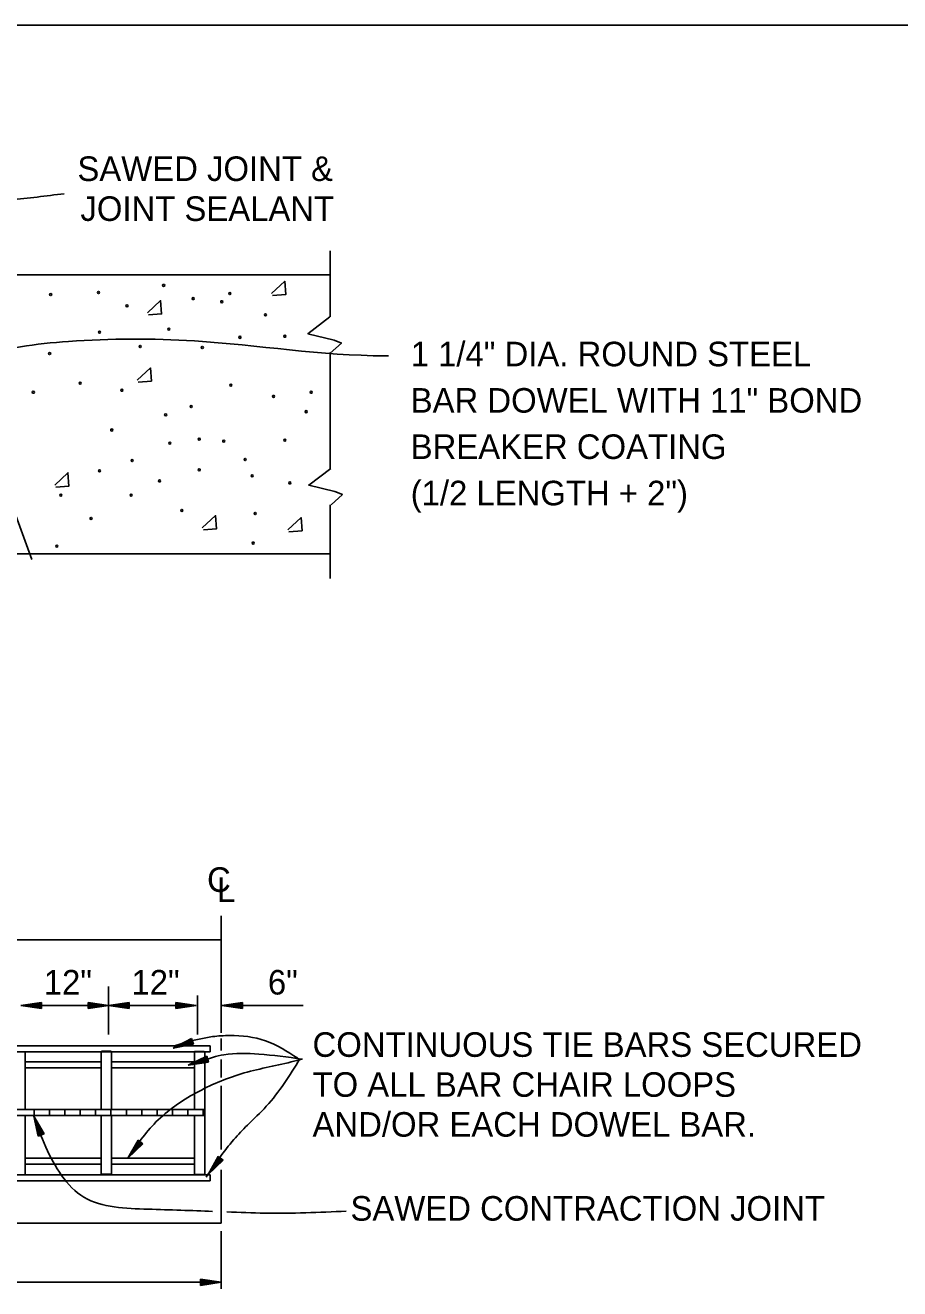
# Model space of a CAD drawing. Extents: x 1375738 to 1375905, y 380661 to 380875.
# Drawn here: x 1375765.86 to 1375781.94, y 380791.56 to 380814.78 of the extents above; entities that cross this region are included whole.
import ezdxf

# ---------------------------------------------------------------- set-up
doc = ezdxf.new("R2010")
doc.units = 0
doc.layers.add('R_Border', color=7, linetype='Continuous')
doc.layers.add('R_Draft', color=7, linetype='Continuous')

msp = doc.modelspace()

# ---------------------------------------------------------------- linework, layer by layer
at = {"layer": 'R_Border'}
msp.add_line((1375744.419, 380814.777), (1375786.095, 380814.777), dxfattribs=at)
at = {"layer": 'R_Draft'}
for p, q in [((1375771.466, 380809.419), (1375771.466, 380810.635)), ((1375759.477, 380810.189), (1375771.466, 380810.189)), ((1375771.466, 380806.625), (1375771.466, 380808.767)), ((1375764.849, 380808.047), (1375765.982, 380804.959)), ((1375771.466, 380804.614), (1375771.466, 380805.963)), ((1375747.021, 380805.063), (1375771.466, 380805.063)), ((1375769.46, 380796.263), (1375769.46, 380798.416)), ((1375759.021, 380797.97), (1375769.46, 380797.97)), ((1375767.391, 380796.231), (1375767.391, 380797.112)), ((1375766.156, 380796.822), (1375765.78, 380796.765)), ((1375765.78, 380796.765), (1375767.391, 380796.765)), ((1375766.156, 380796.709), (1375765.78, 380796.765)), ((1375766.156, 380796.813), (1375765.843, 380796.765)), ((1375766.156, 380796.718), (1375765.843, 380796.765)), ((1375766.156, 380796.803), (1375765.908, 380796.765)), ((1375766.156, 380796.728), (1375765.908, 380796.765)), ((1375766.156, 380796.793), (1375765.97, 380796.765)), ((1375766.156, 380796.738), (1375765.97, 380796.765)), ((1375766.156, 380796.784), (1375766.034, 380796.765)), ((1375766.156, 380796.747), (1375766.034, 380796.765)), ((1375766.156, 380796.774), (1375766.096, 380796.765)), ((1375766.156, 380796.757), (1375766.096, 380796.765)), ((1375766.156, 380796.709), (1375766.156, 380796.822)), ((1375767.015, 380796.822), (1375767.391, 380796.765)), ((1375767.015, 380796.822), (1375767.015, 380796.709)), ((1375767.015, 380796.813), (1375767.328, 380796.765)), ((1375767.015, 380796.803), (1375767.264, 380796.765)), ((1375767.015, 380796.793), (1375767.201, 380796.765)), ((1375767.015, 380796.783), (1375767.137, 380796.765)), ((1375767.015, 380796.774), (1375767.074, 380796.765)), ((1375767.015, 380796.709), (1375767.391, 380796.765)), ((1375767.015, 380796.747), (1375767.137, 380796.765)), ((1375767.015, 380796.728), (1375767.264, 380796.765)), ((1375767.015, 380796.718), (1375767.328, 380796.765)), ((1375767.015, 380796.738), (1375767.201, 380796.765)), ((1375767.015, 380796.757), (1375767.074, 380796.765)), ((1375767.768, 380796.822), (1375767.391, 380796.765)), ((1375767.391, 380796.765), (1375769.003, 380796.765)), ((1375767.768, 380796.709), (1375767.391, 380796.765)), ((1375767.768, 380796.813), (1375767.454, 380796.765)), ((1375767.768, 380796.718), (1375767.454, 380796.765)), ((1375767.768, 380796.803), (1375767.519, 380796.765)), ((1375767.768, 380796.728), (1375767.519, 380796.765)), ((1375767.768, 380796.793), (1375767.581, 380796.765)), ((1375767.768, 380796.738), (1375767.581, 380796.765)), ((1375767.768, 380796.784), (1375767.645, 380796.765)), ((1375767.768, 380796.747), (1375767.645, 380796.765)), ((1375767.768, 380796.774), (1375767.708, 380796.765)), ((1375767.768, 380796.757), (1375767.708, 380796.765)), ((1375767.768, 380796.709), (1375767.768, 380796.822)), ((1375768.626, 380796.822), (1375769.003, 380796.765)), ((1375768.626, 380796.822), (1375768.626, 380796.709)), ((1375768.626, 380796.813), (1375768.94, 380796.765)), ((1375768.626, 380796.803), (1375768.875, 380796.765)), ((1375768.626, 380796.793), (1375768.813, 380796.765)), ((1375768.626, 380796.783), (1375768.749, 380796.765)), ((1375768.626, 380796.774), (1375768.686, 380796.765)), ((1375768.626, 380796.709), (1375769.003, 380796.765)), ((1375768.626, 380796.747), (1375768.749, 380796.765)), ((1375768.626, 380796.728), (1375768.875, 380796.765)), ((1375768.626, 380796.718), (1375768.94, 380796.765)), ((1375768.626, 380796.738), (1375768.813, 380796.765)), ((1375768.626, 380796.757), (1375768.686, 380796.765)), ((1375769.025, 380796.231), (1375769.025, 380796.947)), ((1375769.85, 380796.822), (1375769.473, 380796.765)), ((1375769.473, 380796.765), (1375770.968, 380796.765)), ((1375769.85, 380796.709), (1375769.473, 380796.765)), ((1375769.85, 380796.813), (1375769.536, 380796.765)), ((1375769.85, 380796.718), (1375769.536, 380796.765)), ((1375769.85, 380796.803), (1375769.601, 380796.765)), ((1375769.85, 380796.728), (1375769.601, 380796.765)), ((1375769.85, 380796.793), (1375769.663, 380796.765)), ((1375769.85, 380796.738), (1375769.663, 380796.765)), ((1375769.85, 380796.784), (1375769.727, 380796.765)), ((1375769.85, 380796.747), (1375769.727, 380796.765)), ((1375769.85, 380796.774), (1375769.79, 380796.765)), ((1375769.85, 380796.757), (1375769.79, 380796.765)), ((1375769.85, 380796.709), (1375769.85, 380796.822)), ((1375768.912, 380796.162), (1375768.578, 380795.98)), ((1375768.95, 380796.057), (1375768.578, 380795.98)), ((1375768.914, 380796.154), (1375768.637, 380796.001)), ((1375768.947, 380796.065), (1375768.637, 380796.001)), ((1375768.918, 380796.145), (1375768.697, 380796.023)), ((1375768.944, 380796.074), (1375768.697, 380796.023)), ((1375768.921, 380796.136), (1375768.756, 380796.045)), ((1375768.941, 380796.083), (1375768.756, 380796.045)), ((1375768.925, 380796.127), (1375768.816, 380796.067)), ((1375768.937, 380796.093), (1375768.816, 380796.067)), ((1375768.928, 380796.118), (1375768.875, 380796.089)), ((1375768.934, 380796.101), (1375768.875, 380796.089)), ((1375768.95, 380796.057), (1375768.912, 380796.162)), ((1375769.46, 380795.936), (1375769.46, 380796.159)), ((1375751.127, 380796.025), (1375769.258, 380796.025)), ((1375751.127, 380795.912), (1375769.258, 380795.912)), ((1375765.86, 380794.863), (1375765.86, 380795.926)), ((1375767.257, 380794.863), (1375767.257, 380795.926)), ((1375767.258, 380795.926), (1375767.435, 380795.926)), ((1375767.445, 380794.863), (1375767.445, 380795.926)), ((1375769.194, 380795.832), (1375768.852, 380795.667)), ((1375769.197, 380795.824), (1375768.912, 380795.685)), ((1375768.972, 380794.855), (1375768.972, 380795.919)), ((1375768.973, 380795.919), (1375769.15, 380795.919)), ((1375769.2, 380795.814), (1375768.974, 380795.704)), ((1375769.203, 380795.805), (1375769.033, 380795.723)), ((1375769.16, 380793.662), (1375769.16, 380795.919)), ((1375769.228, 380795.724), (1375769.194, 380795.832)), ((1375769.258, 380796.025), (1375769.258, 380795.912)), ((1375765.86, 380795.731), (1375767.257, 380795.731)), ((1375765.86, 380795.618), (1375767.257, 380795.618)), ((1375767.445, 380795.731), (1375768.966, 380795.731)), ((1375767.445, 380795.618), (1375768.966, 380795.618)), ((1375769.228, 380795.724), (1375768.852, 380795.667)), ((1375769.225, 380795.734), (1375768.912, 380795.685)), ((1375769.222, 380795.743), (1375768.974, 380795.704)), ((1375769.22, 380795.751), (1375769.033, 380795.723)), ((1375769.206, 380795.796), (1375769.094, 380795.742)), ((1375769.217, 380795.76), (1375769.094, 380795.742)), ((1375769.208, 380795.786), (1375769.154, 380795.76)), ((1375769.214, 380795.77), (1375769.154, 380795.76)), ((1375769.46, 380795.442), (1375769.46, 380795.776)), ((1375769.46, 380794.121), (1375769.46, 380795.287)), ((1375751.202, 380794.857), (1375769.16, 380794.857)), ((1375751.202, 380794.744), (1375769.16, 380794.744)), ((1375765.86, 380793.669), (1375765.86, 380794.751)), ((1375766.099, 380794.364), (1375766.016, 380794.735)), ((1375766.205, 380794.405), (1375766.016, 380794.735)), ((1375766.023, 380794.751), (1375766.023, 380794.853)), ((1375766.108, 380794.367), (1375766.038, 380794.677)), ((1375766.196, 380794.401), (1375766.038, 380794.677)), ((1375766.306, 380794.751), (1375766.306, 380794.853)), ((1375766.588, 380794.751), (1375766.588, 380794.853)), ((1375766.87, 380794.751), (1375766.87, 380794.853)), ((1375767.152, 380794.751), (1375767.152, 380794.853)), ((1375767.257, 380793.669), (1375767.257, 380794.751)), ((1375767.434, 380794.751), (1375767.434, 380794.853)), ((1375767.445, 380793.669), (1375767.445, 380794.751)), ((1375767.717, 380794.751), (1375767.717, 380794.853)), ((1375767.999, 380794.751), (1375767.999, 380794.853)), ((1375768.281, 380794.751), (1375768.281, 380794.853)), ((1375768.564, 380794.751), (1375768.564, 380794.853)), ((1375768.846, 380794.751), (1375768.846, 380794.853)), ((1375768.972, 380793.662), (1375768.972, 380794.738)), ((1375769.128, 380794.751), (1375769.128, 380794.853)), ((1375766.187, 380794.398), (1375766.062, 380794.617)), ((1375766.117, 380794.371), (1375766.062, 380794.617)), ((1375766.126, 380794.375), (1375766.084, 380794.558)), ((1375766.178, 380794.394), (1375766.084, 380794.558)), ((1375766.099, 380794.364), (1375766.205, 380794.405)), ((1375766.169, 380794.391), (1375766.108, 380794.498)), ((1375766.135, 380794.378), (1375766.108, 380794.498)), ((1375766.16, 380794.388), (1375766.13, 380794.44)), ((1375766.144, 380794.381), (1375766.13, 380794.44)), ((1375767.933, 380794.293), (1375767.746, 380793.962)), ((1375768.022, 380794.224), (1375767.746, 380793.962)), ((1375767.94, 380794.288), (1375767.785, 380794.012)), ((1375768.015, 380794.23), (1375767.785, 380794.012)), ((1375767.948, 380794.282), (1375767.825, 380794.063)), ((1375768.007, 380794.236), (1375767.825, 380794.063)), ((1375767.955, 380794.276), (1375767.863, 380794.112)), ((1375768, 380794.242), (1375767.863, 380794.112)), ((1375767.963, 380794.27), (1375767.902, 380794.163)), ((1375767.992, 380794.247), (1375767.902, 380794.163)), ((1375768.022, 380794.224), (1375767.933, 380794.293)), ((1375767.97, 380794.265), (1375767.941, 380794.212)), ((1375767.985, 380794.254), (1375767.941, 380794.212)), ((1375765.86, 380793.963), (1375767.257, 380793.963)), ((1375767.445, 380793.963), (1375768.966, 380793.963)), ((1375769.407, 380793.994), (1375769.22, 380793.663)), ((1375769.414, 380793.989), (1375769.259, 380793.713)), ((1375769.422, 380793.983), (1375769.298, 380793.764)), ((1375769.429, 380793.977), (1375769.337, 380793.813)), ((1375769.474, 380793.943), (1375769.337, 380793.813)), ((1375769.437, 380793.971), (1375769.376, 380793.863)), ((1375769.466, 380793.949), (1375769.376, 380793.863)), ((1375769.496, 380793.925), (1375769.407, 380793.994)), ((1375769.444, 380793.965), (1375769.415, 380793.913)), ((1375769.458, 380793.954), (1375769.415, 380793.913)), ((1375765.86, 380793.85), (1375767.257, 380793.85)), ((1375767.445, 380793.85), (1375768.96, 380793.85)), ((1375769.496, 380793.925), (1375769.22, 380793.663)), ((1375769.489, 380793.931), (1375769.259, 380793.713)), ((1375769.481, 380793.937), (1375769.298, 380793.764)), ((1375769.46, 380792.765), (1375769.46, 380793.745)), ((1375751.127, 380793.655), (1375769.258, 380793.655)), ((1375751.127, 380793.542), (1375769.258, 380793.542)), ((1375767.263, 380793.669), (1375767.443, 380793.669)), ((1375768.971, 380793.662), (1375769.16, 380793.662)), ((1375769.258, 380793.655), (1375769.258, 380793.542)), ((1375759.316, 380792.765), (1375769.46, 380792.765)), ((1375769.46, 380791.561), (1375769.46, 380792.618)), ((1375750.756, 380791.679), (1375769.46, 380791.679)), ((1375769.083, 380791.735), (1375769.46, 380791.679)), ((1375769.083, 380791.735), (1375769.083, 380791.622)), ((1375769.083, 380791.725), (1375769.397, 380791.679)), ((1375769.083, 380791.716), (1375769.332, 380791.679)), ((1375769.083, 380791.707), (1375769.27, 380791.679)), ((1375769.083, 380791.697), (1375769.206, 380791.679)), ((1375769.083, 380791.687), (1375769.143, 380791.679)), ((1375769.083, 380791.622), (1375769.46, 380791.679)), ((1375769.083, 380791.66), (1375769.206, 380791.679)), ((1375769.083, 380791.641), (1375769.332, 380791.679)), ((1375769.083, 380791.632), (1375769.397, 380791.679)), ((1375769.083, 380791.651), (1375769.27, 380791.679)), ((1375769.083, 380791.67), (1375769.143, 380791.679))]:
    msp.add_line(p, q, dxfattribs=at)
for points in [[(1375770.386, 380809.848), (1375770.629, 380810.073), (1375770.648, 380809.829), (1375770.405, 380809.811)], [(1375768.104, 380809.492), (1375768.346, 380809.717), (1375768.365, 380809.473), (1375768.122, 380809.455)], [(1375771.46, 380809.418), (1375771.055, 380809.109), (1375771.537, 380808.994), (1375771.672, 380808.937), (1375771.467, 380808.751)], [(1375767.916, 380808.257), (1375768.159, 380808.482), (1375768.178, 380808.238), (1375767.935, 380808.22)], [(1375766.4, 380806.329), (1375766.644, 380806.555), (1375766.662, 380806.311), (1375766.419, 380806.292)], [(1375771.476, 380806.635), (1375771.071, 380806.327), (1375771.553, 380806.211), (1375771.688, 380806.153), (1375771.482, 380805.968)], [(1375769.114, 380805.543), (1375769.357, 380805.768), (1375769.376, 380805.525), (1375769.133, 380805.506)], [(1375770.686, 380805.506), (1375770.929, 380805.731), (1375770.948, 380805.488), (1375770.705, 380805.469)]]:
    msp.add_lwpolyline(points, dxfattribs=at)
for centre in [(1375768.403, 380809.998), (1375766.326, 380809.829), (1375767.205, 380809.867), (1375768.945, 380809.754), (1375769.619, 380809.848), (1375767.729, 380809.623), (1375769.47, 380809.698), (1375770.274, 380809.455), (1375767.224, 380809.137), (1375768.497, 380809.193), (1375769.806, 380809.043), (1375770.63, 380809.062), (1375767.972, 380808.875), (1375769.114, 380808.856), (1375766.307, 380808.744), (1375766.868, 380808.201), (1375769.638, 380808.164), (1375766.007, 380808.033), (1375767.636, 380808.07), (1375770.424, 380807.958), (1375771.116, 380808.033), (1375768.44, 380807.621), (1375768.908, 380807.771), (1375771.023, 380807.677), (1375767.448, 380807.34), (1375769.058, 380807.172), (1375768.515, 380807.097), (1375769.507, 380807.135), (1375770.63, 380807.153), (1375767.823, 380806.779), (1375769.9, 380806.798), (1375767.224, 380806.591), (1375769.058, 380806.61), (1375770.031, 380806.498), (1375768.328, 380806.404), (1375770.723, 380806.367), (1375766.513, 380806.142), (1375767.804, 380806.142), (1375768.739, 380805.862), (1375770.087, 380805.806), (1375767.068, 380805.715), (1375766.438, 380805.207), (1375770.049, 380805.263)]:
    msp.add_circle(centre, 0.0188, dxfattribs=at)
for points in [[(1375766.572, 380811.682), (1375765.583, 380811.569), (1375764, 380811.455), (1375762.219, 380811.201), (1375760.494, 380810.862), (1375759.788, 380810.466), (1375759.392, 380810.183)], [(1375772.536, 380808.703), (1375772.472, 380808.703), (1375768.969, 380808.978), (1375766.652, 380808.967), (1375764.927, 380808.628), (1375764.22, 380808.232), (1375763.824, 380807.949)], [(1375770.867, 380795.797), (1375770.276, 380796.117), (1375769.616, 380796.214), (1375769.303, 380796.193), (1375768.573, 380796.019)], [(1375770.942, 380795.78), (1375770.151, 380795.873), (1375769.512, 380795.86), (1375769.303, 380795.811), (1375769.157, 380795.762)], [(1375770.953, 380795.783), (1375770.747, 380795.729), (1375769.827, 380795.509), (1375768.998, 380795.159), (1375768.262, 380794.625), (1375767.746, 380793.962)], [(1375770.908, 380795.784), (1375770.29, 380794.914), (1375769.943, 380794.566), (1375769.693, 380794.301), (1375769.185, 380793.613)], [(1375769.303, 380792.983), (1375768.115, 380793.023), (1375766.937, 380793.244), (1375766.237, 380794.165), (1375766.016, 380794.735)], [(1375771.76, 380792.987), (1375770.268, 380792.95), (1375769.565, 380792.974)]]:
    msp.add_spline(points, degree=3, dxfattribs=at)

# ---------------------------------------------------------------- texts
for s, height, p in [('SAWED JOINT &', 0.45163, (1375766.818, 380811.916)), ('JOINT SEALANT', 0.45163, (1375766.873, 380811.182)), ('1 1/4" DIA. ROUND STEEL', 0.4516, (1375772.945, 380808.511)), ('BAR DOWEL WITH 11" BOND', 0.4516, (1375772.945, 380807.659)), ('BREAKER COATING', 0.4516, (1375772.945, 380806.808)), ('(1/2 LENGTH + 2")', 0.4516, (1375772.945, 380805.956)), ('C', 0.452, (1375769.201, 380798.853)), ('L', 0.452, (1375769.385, 380798.669)), ('12"', 0.4516, (1375766.199, 380796.967)), ('12"', 0.4516, (1375767.811, 380796.967)), ('6"', 0.4516, (1375770.319, 380796.967)), ('CONTINUOUS TIE BARS SECURED', 0.45163, (1375771.14, 380795.822)), ('TO ALL BAR CHAIR LOOPS', 0.45163, (1375771.14, 380795.088)), ('AND/OR EACH DOWEL BAR.', 0.45163, (1375771.14, 380794.355)), ('SAWED CONTRACTION JOINT', 0.45163, (1375771.838, 380792.812))]:
    msp.add_text(s, height=height, dxfattribs=at).set_placement(p)

doc.saveas('drawing.dxf')
